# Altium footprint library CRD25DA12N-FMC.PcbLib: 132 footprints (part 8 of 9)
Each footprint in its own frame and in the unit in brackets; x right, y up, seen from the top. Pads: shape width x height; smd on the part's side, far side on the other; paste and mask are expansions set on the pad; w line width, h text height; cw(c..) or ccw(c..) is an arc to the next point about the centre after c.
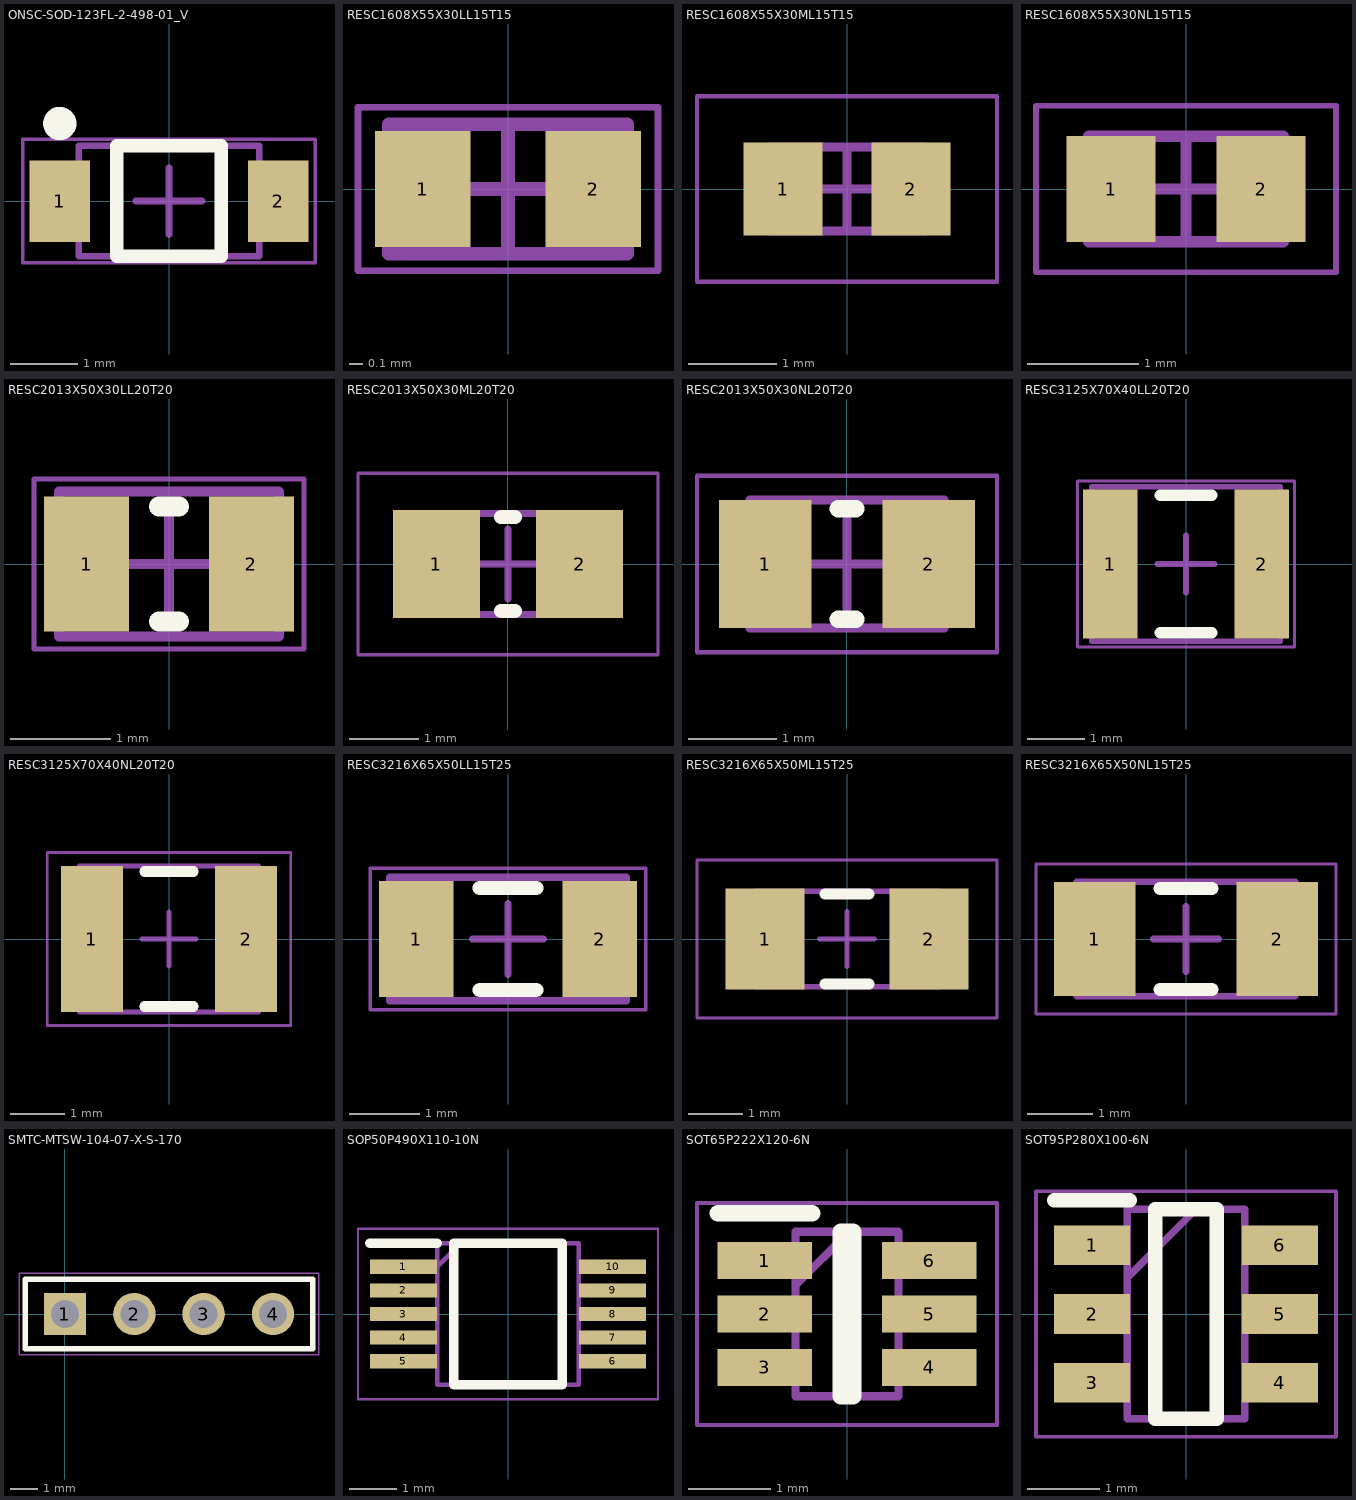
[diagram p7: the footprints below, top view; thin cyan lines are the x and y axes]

## ONSC-SOD-123FL-2-498-01_V [mm] "SOD, 2-Leads, Body 2.7x1.65mm"
height 1
pads (2):
  rect 0.91x1.22 smd: 1(-1.635,0) 2(1.635,0)
Top Overlay:
  circle w0.25: c-1.635,1.16 r0.125
  lines w0.2: -0.78,-0.825 0.78,-0.825 0.78,0.825 -0.78,0.825 -0.78,-0.825
Mechanical 13:
  lines w0.1: -1.35,-0.825 1.35,-0.825 1.35,0.825 -1.35,0.825 -1.35,-0.825
Mechanical 15:
  lines w0.05: -2.19,-0.925 2.19,-0.925 2.19,0.925 -2.19,0.925 -2.19,-0.925
  lines w0.1: -0.5,0 0.5,0 ; 0,-0.5 0,0.5
3D body: height 1, standoff 0, extent -1.35,-0.825 1.35,0.825

## RESC1608X55X30LL15T15 [mm] "Chip Resistor, 2-Leads, Body 1.60x0.80mm, IPC High Density"
height 0.55
pads (2):
  rect 0.7x0.85 smd: 1(-0.625,0) 2(0.625,0)
Mechanical 13:
  lines w0.1: -0.875,-0.475 -0.875,0.475 0.875,0.475 0.875,-0.475 -0.875,-0.475
Mechanical 15:
  lines w0.05: -1.1,-0.6 -1.1,0.6 1.1,0.6 1.1,-0.6 -1.1,-0.6
  lines w0.1: -0.475,0 0.475,0 ; 0,-0.475 0,0.475
3D body: height 0.55, standoff 0, extent -0.575,-0.475 0.575,0.475
3D body: height 0.55, standoff 0, extent -0.875,-0.475 -0.575,0.475
3D body: height 0.55, standoff 0, extent 0.575,-0.475 0.875,0.475

## RESC1608X55X30ML15T15 [mm] "Chip Resistor, 2-Leads, Body 1.60x0.80mm, IPC Low Density"
height 0.55
pads (2):
  rect 0.9x1.05 smd: 1(-0.725,0) 2(0.725,0)
Mechanical 13:
  lines w0.1: -0.875,-0.475 0.875,-0.475 0.875,0.475 -0.875,0.475 -0.875,-0.475
Mechanical 15:
  lines w0.05: -1.7,-1.05 1.7,-1.05 1.7,1.05 -1.7,1.05 -1.7,-1.05
  lines w0.1: -0.475,0 0.475,0 ; 0,-0.475 0,0.475
3D body: height 0.55, standoff 0, extent 0.575,-0.475 0.875,0.475
3D body: height 0.55, standoff 0, extent -0.875,-0.475 -0.575,0.475
3D body: height 0.55, standoff 0, extent -0.575,-0.475 0.575,0.475

## RESC1608X55X30NL15T15 [mm] "Chip Resistor, 2-Leads, Body 1.60x0.80mm, IPC Medium Density"
height 0.55
pads (2):
  rect 0.8x0.95 smd: 1(-0.675,0) 2(0.675,0)
Mechanical 13:
  lines w0.1: -0.875,-0.475 0.875,-0.475 0.875,0.475 -0.875,0.475 -0.875,-0.475
Mechanical 15:
  lines w0.05: -1.35,-0.75 1.35,-0.75 1.35,0.75 -1.35,0.75 -1.35,-0.75
  lines w0.1: -0.475,0 0.475,0 ; 0,-0.475 0,0.475
3D body: height 0.55, standoff 0, extent 0.575,-0.475 0.875,0.475
3D body: height 0.55, standoff 0, extent -0.875,-0.475 -0.575,0.475
3D body: height 0.55, standoff 0, extent -0.575,-0.475 0.575,0.475

## RESC2013X50X30LL20T20 [mm] "Chip Resistor, 2-Leads, Body 2.00x1.25mm, IPC High Density"
height 0.5
pads (2):
  rect 0.85x1.35 smd: 1(-0.825,0) 2(0.825,0)
Top Overlay:
  lines w0.2: -0.1,-0.575 0.1,-0.575 ; -0.1,0.575 0.1,0.575
Mechanical 13:
  lines w0.1: -1.1,-0.725 1.1,-0.725 1.1,0.725 -1.1,0.725 -1.1,-0.725
Mechanical 15:
  lines w0.05: -1.35,-0.85 1.35,-0.85 1.35,0.85 -1.35,0.85 -1.35,-0.85
  lines w0.1: -0.5,0 0.5,0 ; 0,-0.5 0,0.5
3D body: height 0.5, standoff 0, extent 0.8,-0.725 1.1,0.725
3D body: height 0.5, standoff 0, extent -1.1,-0.725 -0.8,0.725
3D body: height 0.5, standoff 0, extent -0.8,-0.725 0.8,0.725

## RESC2013X50X30ML20T20 [mm] "Chip Resistor, 2-Leads, Body 2.00x1.25mm, IPC Low Density"
height 0.5
pads (2):
  rect 1.25x1.55 smd: 1(-1.025,0) 2(1.025,0)
Top Overlay:
  lines w0.2: -0.1,-0.675 0.1,-0.675 ; -0.1,0.675 0.1,0.675
Mechanical 13:
  lines w0.1: -1.1,-0.725 1.1,-0.725 1.1,0.725 -1.1,0.725 -1.1,-0.725
Mechanical 15:
  lines w0.05: -2.15,-1.3 2.15,-1.3 2.15,1.3 -2.15,1.3 -2.15,-1.3
  lines w0.1: -0.5,0 0.5,0 ; 0,-0.5 0,0.5
3D body: height 0.5, standoff 0, extent 0.8,-0.725 1.1,0.725
3D body: height 0.5, standoff 0, extent -1.1,-0.725 -0.8,0.725
3D body: height 0.5, standoff 0, extent -0.8,-0.725 0.8,0.725

## RESC2013X50X30NL20T20 [mm] "Chip Resistor, 2-Leads, Body 2.00x1.25mm, IPC Medium Density"
height 0.5
pads (2):
  rect 1.05x1.45 smd: 1(-0.925,0) 2(0.925,0)
Top Overlay:
  lines w0.2: -0.1,-0.625 0.1,-0.625 ; -0.1,0.625 0.1,0.625
Mechanical 13:
  lines w0.1: -1.1,-0.725 -1.1,0.725 1.1,0.725 1.1,-0.725 -1.1,-0.725
Mechanical 15:
  lines w0.05: -1.7,-1 -1.7,1 1.7,1 1.7,-1 -1.7,-1
  lines w0.1: -0.5,0 0.5,0 ; 0,-0.5 0,0.5
3D body: height 0.5, standoff 0, extent -0.8,-0.725 0.8,0.725
3D body: height 0.5, standoff 0, extent -1.1,-0.725 -0.8,0.725
3D body: height 0.5, standoff 0, extent 0.8,-0.725 1.1,0.725

## RESC3125X70X40LL20T20 [mm] "Chip Resistor, 2-Leads, Body 3.10x2.50mm, IPC High Density"
height 0.7
pads (2):
  rect 0.95x2.6 smd: 1(-1.325,0) 2(1.325,0)
Top Overlay:
  lines w0.2: -0.45,-1.2 0.45,-1.2 ; -0.45,1.2 0.45,1.2
Mechanical 13:
  lines w0.1: -1.65,-1.35 1.65,-1.35 1.65,1.35 -1.65,1.35 -1.65,-1.35
Mechanical 15:
  lines w0.05: -1.9,-1.45 1.9,-1.45 1.9,1.45 -1.9,1.45 -1.9,-1.45
  lines w0.1: -0.5,0 0.5,0 ; 0,-0.5 0,0.5
3D body: height 0.7, standoff 0, extent 1.25,-1.35 1.65,1.35
3D body: height 0.7, standoff 0, extent -1.65,-1.35 -1.25,1.35
3D body: height 0.7, standoff 0, extent -1.25,-1.35 1.25,1.35

## RESC3125X70X40NL20T20 [mm] "Chip Resistor, 2-Leads, Body 3.10x2.50mm, IPC Medium Density"
height 0.7
pads (2):
  rect 1.15x2.7 smd: 1(-1.425,0) 2(1.425,0)
Top Overlay:
  lines w0.2: -0.45,-1.25 0.45,-1.25 ; -0.45,1.25 0.45,1.25
Mechanical 13:
  lines w0.1: -1.65,-1.35 -1.65,1.35 1.65,1.35 1.65,-1.35 -1.65,-1.35
Mechanical 15:
  lines w0.05: -2.25,-1.6 -2.25,1.6 2.25,1.6 2.25,-1.6 -2.25,-1.6
  lines w0.1: -0.5,0 0.5,0 ; 0,-0.5 0,0.5
3D body: height 0.7, standoff 0, extent -1.25,-1.35 1.25,1.35
3D body: height 0.7, standoff 0, extent -1.65,-1.35 -1.25,1.35
3D body: height 0.7, standoff 0, extent 1.25,-1.35 1.65,1.35

## RESC3216X65X50LL15T25 [mm] "Chip Resistor, 2-Leads, Body 3.20x1.60mm, IPC High Density"
height 0.65
pads (2):
  rect 1.05x1.65 smd: 1(-1.3,0) 2(1.3,0)
Top Overlay:
  lines w0.2: -0.4,-0.725 0.4,-0.725 ; -0.4,0.725 0.4,0.725
Mechanical 13:
  lines w0.1: -1.675,-0.875 -1.675,0.875 1.675,0.875 1.675,-0.875 -1.675,-0.875
Mechanical 15:
  lines w0.05: -1.95,-1 -1.95,1 1.95,1 1.95,-1 -1.95,-1
  lines w0.1: -0.5,0 0.5,0 ; 0,-0.5 0,0.5
3D body: height 0.65, standoff 0, extent -1.175,-0.875 1.175,0.875
3D body: height 0.65, standoff 0, extent -1.675,-0.875 -1.175,0.875
3D body: height 0.65, standoff 0, extent 1.175,-0.875 1.675,0.875

## RESC3216X65X50ML15T25 [mm] "Chip Resistor, 2-Leads, Body 3.20x1.60mm, IPC Low Density"
height 0.65
pads (2):
  rect 1.45x1.85 smd: 1(-1.5,0) 2(1.5,0)
Top Overlay:
  lines w0.2: -0.4,-0.825 0.4,-0.825 ; -0.4,0.825 0.4,0.825
Mechanical 13:
  lines w0.1: -1.675,-0.875 -1.675,0.875 1.675,0.875 1.675,-0.875 -1.675,-0.875
Mechanical 15:
  lines w0.05: -2.75,-1.45 -2.75,1.45 2.75,1.45 2.75,-1.45 -2.75,-1.45
  lines w0.1: -0.5,0 0.5,0 ; 0,-0.5 0,0.5
3D body: height 0.65, standoff 0, extent -1.175,-0.875 1.175,0.875
3D body: height 0.65, standoff 0, extent -1.675,-0.875 -1.175,0.875
3D body: height 0.65, standoff 0, extent 1.175,-0.875 1.675,0.875

## RESC3216X65X50NL15T25 [mm] "Chip Resistor, 2-Leads, Body 3.20x1.60mm, IPC Medium Density"
height 0.65
pads (2):
  rect 1.25x1.75 smd: 1(-1.4,0) 2(1.4,0)
Top Overlay:
  lines w0.2: -0.4,-0.775 0.4,-0.775 ; -0.4,0.775 0.4,0.775
Mechanical 13:
  lines w0.1: -1.675,-0.875 -1.675,0.875 1.675,0.875 1.675,-0.875 -1.675,-0.875
Mechanical 15:
  lines w0.05: -2.3,-1.15 -2.3,1.15 2.3,1.15 2.3,-1.15 -2.3,-1.15
  lines w0.1: -0.5,0 0.5,0 ; 0,-0.5 0,0.5
3D body: height 0.65, standoff 0, extent -1.175,-0.875 1.175,0.875
3D body: height 0.65, standoff 0, extent -1.675,-0.875 -1.175,0.875
3D body: height 0.65, standoff 0, extent 1.175,-0.875 1.675,0.875

## SMTC-MTSW-104-07-X-S-170 [mm] "Assembly .025\" [.64] SQ Post Terminal Strip, 1x4 Pins, Vertical, 2.54mm Pitch, Male"
height 7.061
pads (4):
  rect 1.55x1.55 hole 1.02: 1(0,0)
  round 1.55 hole 1.02: 2(2.54,0) 3(5.08,0) 4(7.62,0)
Top Overlay:
  lines w0.2: -1.46,-1.27 -1.46,1.27 9.08,1.27 9.08,-1.27 -1.46,-1.27
Mechanical 13:
  lines w0.1: -1.46,-1.27 -1.46,1.27 9.08,1.27 9.08,-1.27 -1.46,-1.27
Mechanical 15:
  lines w0.05: -1.685,-1.495 -1.685,1.495 9.305,1.495 9.305,-1.495 -1.685,-1.495
3D body "MTSW-104-07-X-S-170.step": height 6.86, standoff -4.06, extent -1.27,-1.27 8.89,1.27

## SOP50P490X110-10N [mm]
pads (10):
  rect 1.425x0.3 smd: 1(-2.212,1) 2(-2.212,0.5) 3(-2.212,0) 4(-2.212,-0.5) 5(-2.212,-1) 6(2.212,-1) 7(2.212,-0.5) 8(2.212,0) 9(2.212,0.5) 10(2.212,1)
Top Overlay:
  lines w0.2: -2.925,1.5 -1.5,1.5 ; -1.15,-1.5 1.15,-1.5 1.15,1.5 -1.15,1.5 -1.15,-1.5
Top Designator:
  text ".Designator" at -7.618,-0.508 h1.52
Mechanical 13:
  lines w0.1: -1.5,1 -1,1.5 ; -1.5,-1.5 1.5,-1.5 1.5,1.5 -1.5,1.5 -1.5,-1.5
Mechanical 15:
  lines w0.05: -3.175,-1.801 3.175,-1.801 3.175,1.801 -3.175,1.801 -3.175,-1.801
3D body "LTC4368IMS-2#PBF.stp": height 1.1, standoff 0, extent -2.45,-1.5 2.45,1.5

## SOT65P222X120-6N [mm]
pads (6):
  rect 1.15x0.45 smd: 1(-1,0.65) 2(-1,0) 3(-1,-0.65) 4(1,-0.65) 5(1,0) 6(1,0.65)
Top Overlay:
  lines w0.2: -1.575,1.225 -0.425,1.225 ; -0.075,-1 0.075,-1 0.075,1 -0.075,1 -0.075,-1
Top Designator:
  text ".Designator" at -7.618,-0.508 h1.52
Mechanical 13:
  lines w0.1: -0.625,0.35 0.025,1 ; -0.625,-1 0.625,-1 0.625,1 -0.625,1 -0.625,-1
Mechanical 15:
  lines w0.05: -1.825,-1.35 1.825,-1.35 1.825,1.35 -1.825,1.35 -1.825,-1.35
3D body "BAS40DW-04-TP.stp": height 1.2, standoff 0, extent -1.112,-1 1.112,1

## SOT95P280X100-6N [mm]
pads (6):
  rect 1.05x0.55 smd: 1(-1.3,0.95) 2(-1.3,0) 3(-1.3,-0.95) 4(1.3,-0.95) 5(1.3,0) 6(1.3,0.95)
Top Overlay:
  lines w0.2: -1.825,1.575 -0.775,1.575 ; -0.425,-1.45 0.425,-1.45 0.425,1.45 -0.425,1.45 -0.425,-1.45
Mechanical 13:
  lines w0.1: -0.812,0.5 0.138,1.45 ; -0.812,-1.45 0.812,-1.45 0.812,1.45 -0.812,1.45 -0.812,-1.45
Mechanical 15:
  lines w0.05: -2.075,-1.7 2.075,-1.7 2.075,1.7 -2.075,1.7 -2.075,-1.7
3D body "LTC6992CS6-2#TRMPBF.stp": height 1, standoff 0, extent -1.4,-1.45 1.4,1.45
